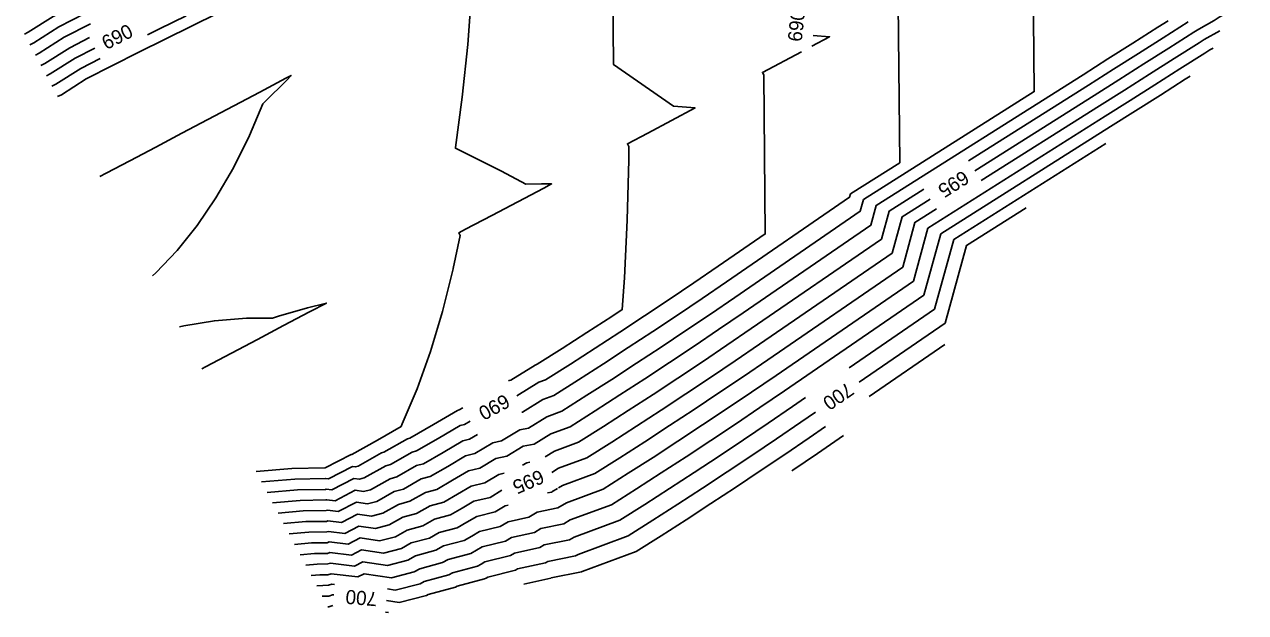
# Model space of a CAD drawing. Extents: x 1487507 to 1489130, y 497211 to 499439.
# Drawn here: x 1487820.3 to 1488027.8, y 498340 to 498440 of the extents above; entities that cross this region are included whole.
import ezdxf

# ---------------------------------------------------------------- set-up
doc = ezdxf.new("R2010")
doc.units = 0
for name, color, linetype in [('Prop CMT Ditch DDE', 7, 'Continuous'), ('Prop Drainage Ditch Flow Line', 7, 'Continuous'), ('Prop Drainage Structure Pipe Outlet Channel Detail CELL', 7, 'Continuous')]:
    doc.layers.add(name, color=color, linetype=linetype)

msp = doc.modelspace()

# ---------------------------------------------------------------- linework, layer by layer
at = {"layer": 'Prop CMT Ditch DDE'}
for points in [[(1487920.14, 498463.54), (1487920.43, 498433.15), (1487930.6, 498426.09), (1487934.28, 498425.77), (1487926.23, 498421.51), (1487922.77, 498419.68), (1487923, 498419.23), (1487923, 498416.93), (1487922.76, 498406.69), (1487922.3, 498396.88), (1487921.91, 498391.5), (1487920.12, 498390.32), (1487915.91, 498387.58), (1487911.68, 498384.87), (1487907.45, 498382.19), (1487907.09, 498382.06), (1487902.96, 498379.5), (1487902.95, 498379.49), (1487902.71, 498379.44), (1487902.6, 498379.38)], [(1487820.33, 498438.3), (1487820.99, 498438.64), (1487825.23, 498441.32), (1487829.68, 498443.61), (1487834.15, 498445.85), (1487838.62, 498448.08), (1487843.11, 498450.29), (1487847.6, 498452.49), (1487852.11, 498454.67), (1487856.62, 498456.83), (1487861.15, 498458.97), (1487861.16, 498458.97), (1487862.37, 498459.55)], [(1487991.73, 498447.41), (1487991.91, 498428.56), (1487962.87, 498410.19), (1487962.33, 498408.22), (1487941.03, 498393.57), (1487936.87, 498390.73), (1487932.7, 498387.92), (1487928.52, 498385.13), (1487924.33, 498382.37), (1487920.12, 498379.63), (1487915.9, 498376.92), (1487911.66, 498374.23), (1487909.08, 498373.28), (1487905.96, 498371.34), (1487905.96, 498371.34), (1487904.49, 498371.05), (1487901.39, 498369.17), (1487899.89, 498368.83), (1487896.83, 498367), (1487895.3, 498366.62), (1487892.26, 498364.84), (1487889.27, 498363.1), (1487887.72, 498362.69), (1487884.73, 498360.98), (1487883.18, 498360.56), (1487880.19, 498358.86), (1487878.62, 498358.46), (1487876.73, 498358.74), (1487873.66, 498357.15), (1487871.8, 498357.38), (1487871.58, 498357.31), (1487867.68, 498357.25), (1487863.44, 498356.88)], [(1487859.69, 498363.95), (1487865.77, 498364.48), (1487871.35, 498364.56), (1487871.36, 498364.57), (1487871.45, 498364.56), (1487875.86, 498366.85), (1487875.92, 498366.84), (1487875.97, 498366.85), (1487880.3, 498369.3), (1487880.32, 498369.31), (1487884.32, 498371.6), (1487884.53, 498372.04), (1487887.04, 498378), (1487889.32, 498384.38), (1487891.37, 498391.19), (1487893.19, 498398.43), (1487893.19, 498398.45), (1487894.37, 498404.08), (1487894.13, 498404.52), (1487895.3, 498405.14), (1487899.72, 498407.48), (1487904.14, 498409.81), (1487908.56, 498412.15), (1487909.89, 498412.86), (1487908.18, 498412.86), (1487905.5, 498412.8), (1487901.38, 498415.02), (1487893.69, 498418.87), (1487893.56, 498418.93), (1487893.59, 498419.06), (1487894.73, 498427.59), (1487895.65, 498436.55), (1487896.29, 498445.26)], [(1487904.85, 498374.04), (1487904.95, 498374.06), (1487904.96, 498374.06), (1487908.42, 498376.21), (1487910.26, 498376.89), (1487914.49, 498379.57), (1487918.71, 498382.28), (1487922.92, 498385.02), (1487927.12, 498387.78), (1487931.3, 498390.57), (1487935.47, 498393.38), (1487939.62, 498396.22), (1487960.52, 498410.59), (1487960.68, 498411.16), (1487969.05, 498416.46), (1487968.8, 498443.48)], [(1487821.27, 498436.53), (1487821.93, 498436.87), (1487826.17, 498439.55), (1487830.61, 498441.84)], [(1487853.22, 498441.88), (1487848.72, 498439.69), (1487844.24, 498437.48), (1487839.76, 498435.25), (1487835.29, 498433), (1487830.84, 498430.72), (1487826.61, 498428.03), (1487825.95, 498427.7)], [(1487841.22, 498438.21), (1487843.3, 498439.24), (1487847.79, 498441.46)], [(1488014.65, 498440.59), (1488012.9, 498439.48), (1488008.66, 498436.8), (1488004.42, 498434.11), (1488000.19, 498431.43), (1487965.06, 498409.21), (1487964.13, 498405.84), (1487942.43, 498390.92), (1487938.28, 498388.08), (1487934.11, 498385.26), (1487929.93, 498382.48), (1487925.73, 498379.71), (1487921.52, 498376.98), (1487917.3, 498374.27), (1487913.06, 498371.58), (1487909.75, 498370.36), (1487906.96, 498368.63), (1487906.96, 498368.62), (1487905.08, 498368.26), (1487902.32, 498366.58), (1487900.42, 498366.15), (1487897.7, 498364.52), (1487895.77, 498364.05), (1487893.08, 498362.47), (1487890.42, 498360.92), (1487888.48, 498360.42), (1487885.83, 498358.9), (1487883.9, 498358.37), (1487881.25, 498356.87), (1487879.3, 498356.36), (1487876.94, 498356.71), (1487874.22, 498355.3), (1487871.91, 498355.58), (1487871.63, 498355.49), (1487868.16, 498355.44), (1487864.37, 498355.11)], [(1487822.21, 498434.77), (1487822.86, 498435.1), (1487827.1, 498437.79), (1487831.55, 498440.07)], [(1488018.07, 498440.4), (1488013.83, 498437.71), (1488009.6, 498435.03), (1488005.36, 498432.35), (1488001.12, 498429.66), (1487980.75, 498416.78)], [(1488023.44, 498438.89), (1488020.79, 498437.4), (1488019.94, 498436.87), (1488015.7, 498434.18), (1488011.47, 498431.49), (1488007.23, 498428.81), (1488002.99, 498426.13), (1487982.88, 498413.41)], [(1487831.37, 498437.73), (1487828.04, 498436.02), (1487823.8, 498433.34), (1487823.14, 498433)], [(1487868.12, 498348.04), (1487870.07, 498348.21), (1487871.86, 498348.24), (1487872.35, 498348.39), (1487876.43, 498347.89), (1487877.81, 498348.61), (1487882, 498347.98), (1487885.48, 498348.88), (1487886.78, 498349.62), (1487890.24, 498350.57), (1487891.54, 498351.31), (1487895.03, 498352.22), (1487896.33, 498352.97), (1487897.64, 498353.75), (1487901.17, 498354.62), (1487902.53, 498355.43), (1487906.05, 498356.21), (1487907.46, 498357.07), (1487910.96, 498357.76), (1487910.96, 498357.76), (1487912.41, 498358.66), (1487918.68, 498360.98), (1487922.91, 498363.66), (1487927.14, 498366.37), (1487931.35, 498369.11), (1487935.54, 498371.87), (1487939.72, 498374.66), (1487943.89, 498377.47), (1487948.04, 498380.31), (1487971.36, 498396.34), (1487973.83, 498405.32), (1488003.93, 498424.36), (1488008.17, 498427.04), (1488012.4, 498429.73), (1488016.64, 498432.41), (1488020.87, 498435.1), (1488021.72, 498435.64), (1488022.3, 498435.96)], [(1487825.01, 498429.46), (1487825.67, 498429.8), (1487829.91, 498432.48), (1487833.18, 498434.16)], [(1487833.15, 498414.1), (1487834.2, 498414.66), (1487838.22, 498416.78), (1487842.64, 498419.12), (1487847.06, 498421.46), (1487851.48, 498423.8), (1487855.89, 498426.14), (1487860.31, 498428.48), (1487864.73, 498430.82), (1487865.64, 498431.3), (1487864.9, 498430.51), (1487861.19, 498426.82), (1487860.84, 498426.5), (1487858.57, 498421.09), (1487855.84, 498415.57), (1487852.88, 498410.47), (1487849.69, 498405.8), (1487846.28, 498401.56), (1487842.64, 498397.74), (1487842.08, 498397.22)], [(1488018.39, 498431.16), (1488017.57, 498430.64), (1488013.34, 498427.96), (1488009.1, 498425.28), (1488004.86, 498422.59), (1487976.03, 498404.35), (1487973.16, 498393.96), (1487949.45, 498377.66), (1487945.29, 498374.82), (1487941.13, 498372.01), (1487936.94, 498369.22), (1487932.75, 498366.46), (1487928.54, 498363.72), (1487924.32, 498361.01), (1487920.08, 498358.32), (1487913.08, 498355.73), (1487911.96, 498355.04), (1487911.96, 498355.04), (1487908.05, 498354.27), (1487906.98, 498353.62), (1487903.06, 498352.75), (1487902.04, 498352.14), (1487898.11, 498351.17), (1487897.14, 498350.6), (1487896.18, 498350.04), (1487892.3, 498349.03), (1487891.35, 498348.49), (1487887.51, 498347.43), (1487886.54, 498346.88), (1487882.68, 498345.89), (1487878.03, 498346.58), (1487876.99, 498346.04), (1487872.46, 498346.59), (1487871.91, 498346.42), (1487870.54, 498346.4), (1487869.05, 498346.27)], [(1488004.06, 498419.73), (1487978.22, 498403.38), (1487974.97, 498391.59), (1487960.46, 498381.61)], [(1487973.14, 498411.97), (1487967.26, 498408.24), (1487965.94, 498403.47), (1487943.83, 498388.26), (1487939.68, 498385.43), (1487935.51, 498382.61), (1487931.33, 498379.82), (1487927.13, 498377.06), (1487922.93, 498374.33), (1487918.7, 498371.62), (1487914.47, 498368.93), (1487910.41, 498367.43), (1487908.79, 498366.43)], [(1487975.28, 498408.6), (1487971.64, 498406.3), (1487969.55, 498398.71), (1487946.64, 498382.96), (1487942.49, 498380.12), (1487938.32, 498377.31), (1487934.14, 498374.52), (1487929.94, 498371.76), (1487925.73, 498369.02), (1487921.51, 498366.31), (1487917.27, 498363.63), (1487911.75, 498361.58), (1487911.08, 498361.17)], [(1487846.67, 498388.56), (1487847.42, 498388.72), (1487852.61, 498389.59), (1487858.04, 498390.03), (1487862.49, 498390.03), (1487863.52, 498390.36), (1487868.42, 498391.78), (1487871.63, 498392.6), (1487868.79, 498391.1), (1487864.37, 498388.76), (1487859.95, 498386.42), (1487855.53, 498384.08), (1487851.11, 498381.74), (1487850.46, 498381.4)], [(1487963.84, 498376.7), (1487976.72, 498385.56)], [(1487953.05, 498376.52), (1487950.85, 498375.01), (1487946.7, 498372.17), (1487942.53, 498369.35), (1487938.35, 498366.57), (1487934.15, 498363.8), (1487929.94, 498361.07), (1487925.72, 498358.36), (1487921.49, 498355.67), (1487913.74, 498352.81), (1487912.96, 498352.33), (1487912.96, 498352.32), (1487908.65, 498351.48), (1487907.92, 498351.03), (1487903.59, 498350.07), (1487902.91, 498349.66), (1487898.58, 498348.6), (1487897.95, 498348.23), (1487897.33, 498347.87), (1487893.07, 498346.76), (1487892.45, 498346.4), (1487888.23, 498345.25), (1487887.59, 498344.89), (1487883.35, 498343.79), (1487882, 498343.99)], [(1487894.84, 498374.8), (1487894.22, 498374.43), (1487893.89, 498374.35), (1487889.83, 498371.96), (1487885.81, 498369.62), (1487885.43, 498369.52), (1487881.42, 498367.23), (1487881.02, 498367.12), (1487877.02, 498364.85), (1487876.59, 498364.74), (1487876.08, 498364.82), (1487872, 498362.7), (1487871.47, 498362.77), (1487871.41, 498362.75), (1487866.25, 498362.67), (1487860.63, 498362.18)], [(1487862.5, 498358.65), (1487867.2, 498359.06), (1487871.52, 498359.12), (1487871.69, 498359.17), (1487873.11, 498359), (1487876.51, 498360.77), (1487877.94, 498360.55), (1487879.14, 498360.86), (1487882.46, 498362.74), (1487883.63, 498363.06), (1487886.96, 498364.97), (1487888.12, 498365.27), (1487891.45, 498367.21), (1487894.83, 498369.2), (1487895.96, 498369.48), (1487897.3, 498370.28)], [(1487905.17, 498344.82), (1487909.78, 498345.85), (1487909.83, 498345.88), (1487914.96, 498346.89), (1487915.07, 498346.96), (1487924.29, 498350.37), (1487928.53, 498353.05), (1487932.75, 498355.76), (1487936.96, 498358.5), (1487941.16, 498361.26), (1487945.34, 498364.05), (1487949.5, 498366.86), (1487953.66, 498369.7), (1487956.42, 498371.6)], [(1487959.48, 498370.09), (1487955.06, 498367.05), (1487950.91, 498364.21), (1487950.71, 498364.08)], [(1487901.85, 498363.67), (1487900.95, 498363.47), (1487898.57, 498362.05), (1487896.23, 498361.47), (1487893.89, 498360.09), (1487891.57, 498358.74), (1487889.25, 498358.14), (1487886.94, 498356.82), (1487884.62, 498356.18), (1487882.31, 498354.87), (1487879.97, 498354.27), (1487877.16, 498354.69), (1487874.77, 498353.45), (1487872.02, 498353.78), (1487871.69, 498353.68), (1487868.64, 498353.63), (1487865.31, 498353.34)], [(1487906.2, 498365.56), (1487905.68, 498365.46), (1487904.96, 498365.02)], [(1487910.92, 498361.07), (1487909.96, 498360.48), (1487909.96, 498360.47), (1487909.2, 498360.33)], [(1487902.54, 498358.23), (1487902, 498358.11), (1487900.31, 498357.09), (1487897.17, 498356.32), (1487895.51, 498355.35), (1487893.88, 498354.39), (1487890.77, 498353.59), (1487889.14, 498352.65), (1487886.06, 498351.81), (1487884.42, 498350.88), (1487881.32, 498350.08), (1487877.6, 498350.64), (1487875.88, 498349.74), (1487872.24, 498350.19), (1487871.8, 498350.05), (1487869.59, 498350.02), (1487867.18, 498349.81)], [(1487873.04, 498344.74), (1487872.57, 498344.79), (1487871.97, 498344.61), (1487871.02, 498344.59), (1487869.99, 498344.5)], [(1487872.74, 498341.19), (1487872.08, 498340.98), (1487871.98, 498340.98), (1487871.86, 498340.97)], [(1487882.21, 498339.98), (1487881.68, 498340.05)]]:
    msp.add_lwpolyline(points, dxfattribs=at)
at = {"layer": 'Prop Drainage Ditch Flow Line'}
for points in [[(1487981.82, 498415.09), (1488002.06, 498427.9), (1488006.29, 498430.58), (1488010.53, 498433.26), (1488014.77, 498435.95), (1488019, 498438.63), (1488019.85, 498439.17), (1488022.49, 498440.65), (1488023.31, 498441.18), (1488027.58, 498443.68), (1488027.63, 498443.71), (1488027.81, 498443.81)], [(1487954.13, 498436.28), (1487957.13, 498437.87), (1487954.33, 498438.11)], [(1487832.27, 498435.95), (1487828.97, 498434.25), (1487824.73, 498431.57), (1487824.08, 498431.23)], [(1487904, 498376.8), (1487907.75, 498379.13), (1487908.85, 498379.54), (1487913.09, 498382.22), (1487917.31, 498384.93), (1487921.52, 498387.67), (1487925.71, 498390.43), (1487929.9, 498393.22), (1487934.06, 498396.03), (1487938.22, 498398.87), (1487946.2, 498404.36), (1487945.94, 498431.38), (1487945.71, 498431.82), (1487952.36, 498435.34)], [(1487909.93, 498363.8), (1487911.08, 498364.51), (1487915.87, 498366.28), (1487920.11, 498368.96), (1487924.33, 498371.67), (1487928.54, 498374.41), (1487932.73, 498377.17), (1487936.91, 498379.96), (1487941.08, 498382.77), (1487945.24, 498385.61), (1487967.75, 498401.09), (1487969.45, 498407.27), (1487974.21, 498410.28)], [(1487990.53, 498408.8), (1487980.41, 498402.41), (1487976.77, 498389.21), (1487962.15, 498379.16)], [(1487954.74, 498374.06), (1487952.26, 498372.35), (1487948.1, 498369.52), (1487943.93, 498366.7), (1487939.75, 498363.91), (1487935.56, 498361.15), (1487931.35, 498358.42), (1487927.12, 498355.71), (1487922.89, 498353.02), (1487914.41, 498349.88), (1487913.96, 498349.61), (1487913.96, 498349.61), (1487909.24, 498348.68), (1487908.85, 498348.44), (1487904.12, 498347.39), (1487903.78, 498347.18), (1487899.05, 498346.02), (1487898.76, 498345.85), (1487898.48, 498345.69), (1487893.83, 498344.48), (1487893.55, 498344.32), (1487888.95, 498343.06), (1487888.65, 498342.89), (1487884.03, 498341.7), (1487881.84, 498342.02)], [(1487861.57, 498360.41), (1487866.73, 498360.86), (1487871.47, 498360.93), (1487871.58, 498360.97), (1487872.55, 498360.85), (1487876.29, 498362.79), (1487877.27, 498362.65), (1487878.08, 498362.86), (1487881.74, 498364.93), (1487882.53, 498365.14), (1487886.19, 498367.25), (1487886.96, 498367.45), (1487890.64, 498369.59), (1487894.36, 498371.78), (1487895.09, 498371.96), (1487896.07, 498372.54)], [(1487866.24, 498351.57), (1487869.11, 498351.82), (1487871.75, 498351.86), (1487872.13, 498351.98), (1487875.32, 498351.6), (1487877.38, 498352.66), (1487880.65, 498352.17), (1487883.36, 498352.87), (1487885.34, 498353.99), (1487888.04, 498354.73), (1487890.01, 498355.86), (1487892.72, 498356.57), (1487894.7, 498357.72), (1487896.7, 498358.9), (1487899.44, 498359.57), (1487901.44, 498360.77)], [(1487872.89, 498342.97), (1487872.68, 498343), (1487872.03, 498342.79), (1487871.5, 498342.79), (1487870.92, 498342.74)]]:
    msp.add_lwpolyline(points, dxfattribs=at)

# ---------------------------------------------------------------- texts
at = {"layer": 'Prop Drainage Structure Pipe Outlet Channel Detail CELL'}
for s, rotation, p in [('690', 83.8678, (1487952.39, 498436.95)), ('690', 26.925, (1487834.25, 498435.59)), ('695', 212.3178, (1487979.83, 498415.26)), ('700', 214.5135, (1487960.15, 498379.24)), ('690', 208.5487, (1487901.94, 498377.23)), ('695', 203.4877, (1487907.95, 498364.36)), ('700', 175.2517, (1487880.35, 498343.44))]:
    msp.add_text(s, height=2.4, rotation=rotation, dxfattribs=at).set_placement(p)

doc.saveas('drawing.dxf')
